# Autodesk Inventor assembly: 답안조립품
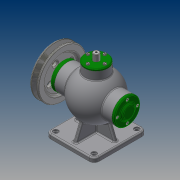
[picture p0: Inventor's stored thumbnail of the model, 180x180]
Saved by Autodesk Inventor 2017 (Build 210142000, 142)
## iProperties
Part Number: 답안조립품
Material: 일반
Document SubType Name: Assembly
Designer: 13
Author: 13
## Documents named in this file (19)
- C:\Users\13\Desktop\480414V1001\답안조립품.iam
- C:\Users\13\Desktop\480414V1001\본체.ipt
- C:\Users\13\Desktop\480414V1001\뒤커버.ipt
- C:\Users\13\Desktop\480414V1001\앞커버.ipt
- C:\Users\13\Desktop\480414V1001\베어링 6202.ipt
- 베어링 6202.ipt
- C:\Users\13\Desktop\480414V1001\상부커버.ipt
- C:\Users\13\Desktop\480414V1001\부시.ipt
- C:\Users\13\Desktop\480414V1001\오일 실 15 30 7.ipt
- C:\Users\13\Desktop\480414V1001\편심축.ipt
- C:\Users\13\Desktop\480414V1001\멈춤링 15x1.ipt
- C:\Users\13\Desktop\480414V1001\멈춤링 35x1.6.ipt
- 멈춤링 35x1.6.ipt
- C:\Users\13\Desktop\480414V1001\슬라이드.ipt
- C:\Users\13\Desktop\480414V1001\키 4x4x12.ipt
- C:\Users\13\Desktop\480414V1001\V-벨트풀리.ipt
- C:\Users\13\Desktop\480414V1001\너트 M8.ipt
- C:\Users\13\Desktop\480414V1001\볼트 M4x16.ipt
- C:\Users\13\Desktop\480414V1001\볼트 M4x12.ipt
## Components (1 placed, 1 different names)
1. V-벨트풀리:1 — 플러쉬:1
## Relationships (1: Flush 1)
- 플러쉬:1 [Flush]: V-벨트풀리:1
